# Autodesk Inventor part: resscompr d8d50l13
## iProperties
Author: chr
Shininess: 20.0
Angle Display Precision: 2
Document Length Units: 11269
Document Angle Units: 11283
Document Time Units: 11279
Document Mass Units: 11290
Document Length Units Precision: 3
Document Angle Units Precision: 2
Compacted: False
PropertySet Name: _Private Model Information
Created: 2002-03
Part Number: resscompr d8d50l13
Material: Par défaut
Document SubType Name: Modélisation
Designer: chr
Control State: 0
Master: False
Checked Out: False
PropertySet Name: Design Tracking Control
Density: 0.0
Volumn: 0.0
Area: 0.0
PropertySet Name: Model Information
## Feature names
1. Base1
